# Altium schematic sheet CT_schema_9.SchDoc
size 391 x 238 mm
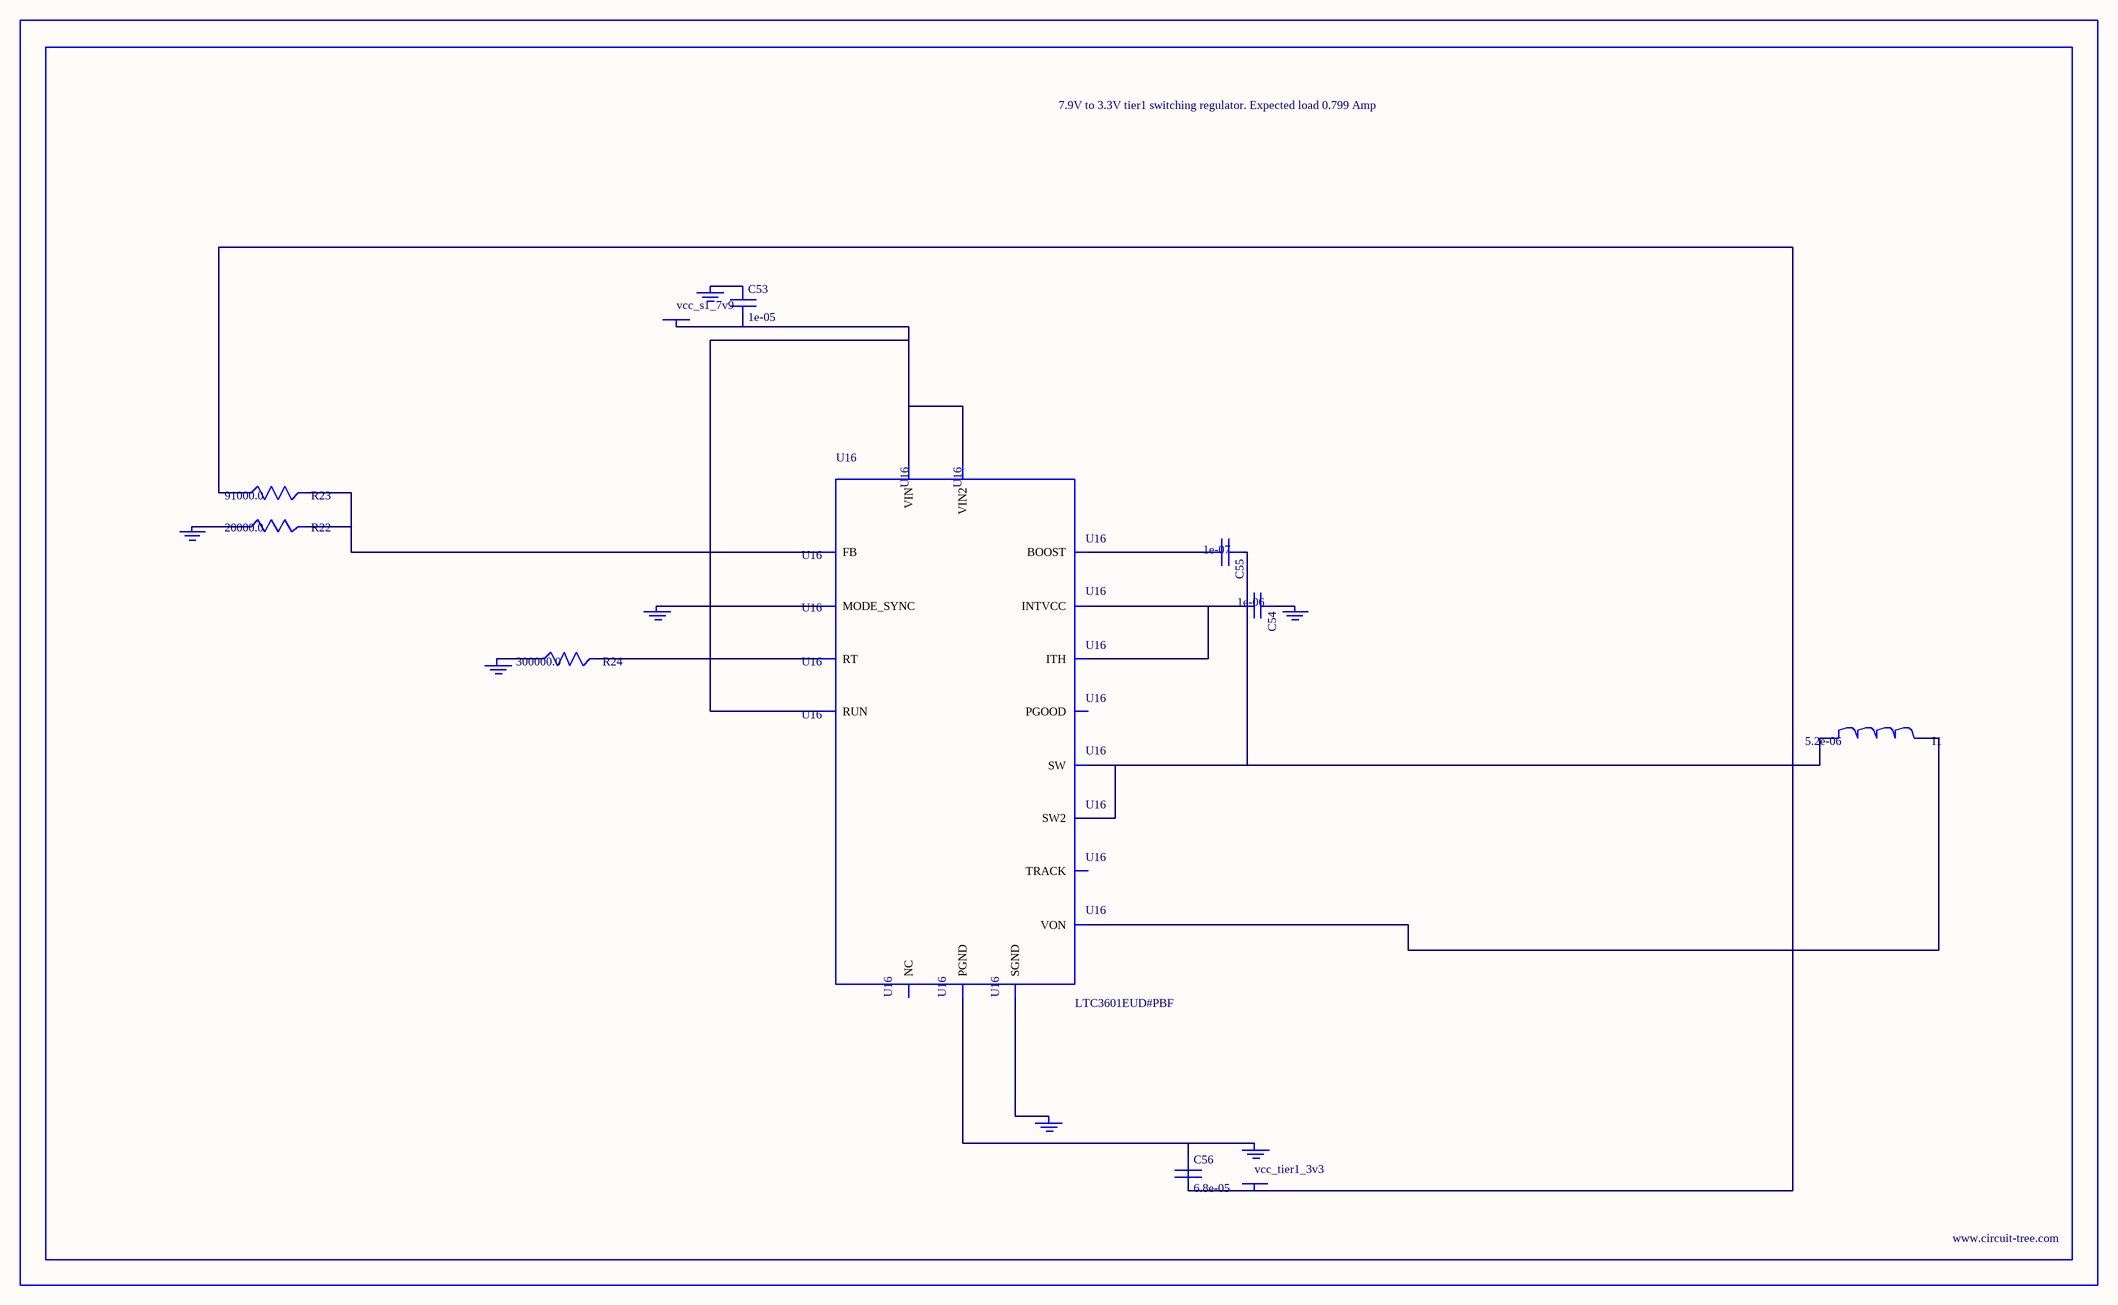
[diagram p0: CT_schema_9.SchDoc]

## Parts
BORDER8  (no value)
C53  1e-05  [C0805]
C54  1e-06  [C0603]
C55  1e-07  [C0402]
C56  6.8e-05  [2220]
GND_INSTANCE_8_0  (no value)
GND_INSTANCE_8_1  (no value)
GND_INSTANCE_8_2  (no value)
GND_INSTANCE_8_3  (no value)
GND_INSTANCE_8_4  (no value)
GND_INSTANCE_8_5  (no value)
GND_INSTANCE_8_6  (no value)
I1  5.2e-06  [DR1040]
POWER_INSTANCE_8_0  vcc_s1_7v9
POWER_INSTANCE_8_1  vcc_tier1_3v3
R22  20000.0  [R0603]
R23  91000.0  [R0603]
R24  300000.0  [R0603]
U16  LTC3601EUD#PBF  [QFN-16_EP]

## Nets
NetC53_1: C53.1 GND_INSTANCE_8_5.0(GND)
NetC53_2: C53.2 POWER_INSTANCE_8_0.0(PWR) U16.14(RUN) U16.15(VIN) U16.16(VIN2)
NetC54_1: C54.1 GND_INSTANCE_8_1.0(GND)
NetC54_2: C54.2 U16.7(INTVCC) U16.12(ITH)
NetC55_1: C55.1 I1.1 U16.3(SW) U16.4(SW2)
NetC55_2: C55.2 U16.6(BOOST)
NetC56_1: C56.1 GND_INSTANCE_8_6.0(GND) U16.17(PGND)
NetC56_2: C56.2 I1.2 POWER_INSTANCE_8_1.0(PWR) R23.1 U16.8(VON)
NetGND_INSTANCE_8_0_0: GND_INSTANCE_8_0.0(GND) U16.1(MODE_SYNC)
NetGND_INSTANCE_8_2_0: GND_INSTANCE_8_2.0(GND) U16.9(SGND)
NetGND_INSTANCE_8_3_0: GND_INSTANCE_8_3.0(GND) R24.1
NetGND_INSTANCE_8_4_0: GND_INSTANCE_8_4.0(GND) R22.1
NetR22_2: R22.2 R23.2 U16.11(FB)
NetR24_2: R24.2 U16.10(RT)

Not connected (* = marked no-connect by the designer): U16 2(PGOOD) 5(NC) 13(TRACK)

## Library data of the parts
BORDER8 = BORDER_PAGE8
C53 = C0805C106K8RACTU
C54 = C0603C105K3RACTU
C55 = C0402C104K3RACTU
C56 = C5750X5R1A686M
GND_INSTANCE_8_0-GND_INSTANCE_8_6 = GND
I1 = DR1040-5R2-R
POWER_INSTANCE_8_0 POWER_INSTANCE_8_1 = PWR
R22 = RC0603JR-0720KL
R23 = RC0603JR-0791KL
R24 = RC0603JR-07300KL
